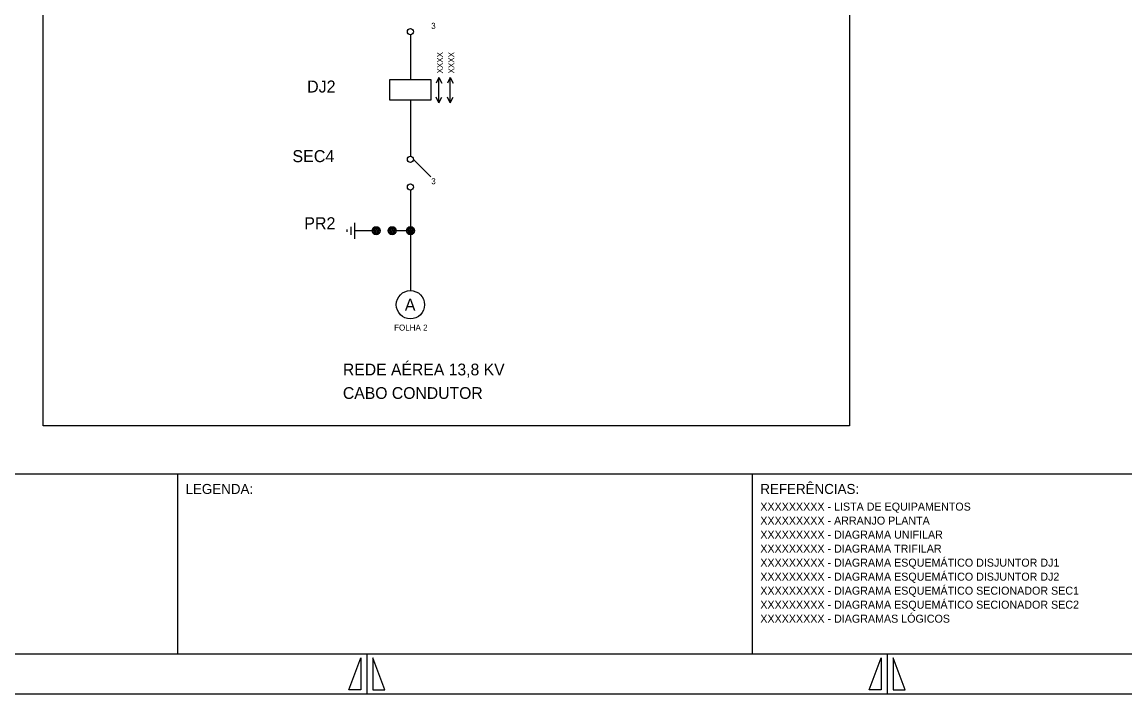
# Model space of a CAD drawing. Extents: x 563 to 1404, y 358 to 952.
# Drawn here: x 817.4 to 1093.1, y 358 to 525.8 of the extents above; entities that cross this region are included whole.
import ezdxf

# ---------------------------------------------------------------- set-up
doc = ezdxf.new("R2010")
doc.units = 0
doc.layers.add('New Level (0)', color=7, linetype='Continuous')

msp = doc.modelspace()

# ---------------------------------------------------------------- linework, layer by layer
for p, q in [((909.34, 506.3), (909.34, 511.42)), ((909.34, 511.42), (919.58, 511.42)), ((919.58, 511.42), (919.58, 506.3)), ((921.58, 511.96), (920.87, 510.55)), ((921.58, 505.6), (921.58, 511.96)), ((921.58, 511.96), (922.28, 510.55)), ((924.43, 511.96), (923.72, 510.55)), ((924.43, 505.6), (924.43, 511.96)), ((924.43, 511.96), (925.13, 510.55)), ((919.58, 506.3), (909.34, 506.3)), ((921.58, 505.6), (920.87, 507.01)), ((921.58, 505.6), (922.28, 507.01)), ((924.43, 505.6), (923.72, 507.01)), ((924.43, 505.6), (925.13, 507.01)), ((919.57, 487.15), (915.23, 491.49)), ((899.57, 474.68), (899.57, 472.68)), ((900.57, 471.68), (900.57, 475.68)), ((898.57, 473.98), (898.57, 473.38)), ((898.57, 473.68), (898.57, 473.68)), ((901.89, 473.68), (900.57, 473.68)), ((905.89, 473.68), (901.89, 473.68)), ((914.47, 473.68), (909.89, 473.68))]:
    msp.add_line(p, q)
for centre, radius in [((914.46, 523.39), 0.768), ((914.46, 491.49), 0.768), ((914.46, 484.59), 0.768), ((905.89, 473.68), 1), ((905.89, 473.68), 0.75), ((905.89, 473.68), 0.5), ((909.89, 473.68), 1), ((909.89, 473.68), 0.75), ((909.89, 473.68), 0.5), ((914.47, 473.68), 1), ((914.47, 473.68), 0.75), ((914.47, 473.68), 0.5), ((905.89, 473.68), 0.25), ((909.89, 473.68), 0.25), ((914.47, 473.68), 0.25)]:
    msp.add_circle(centre, radius)
at = {"layer": 'New Level (0)'}
for p, q in [((914.46, 522.63), (914.46, 511.42)), ((914.46, 506.3), (914.46, 492.26)), ((914.46, 483.82), (914.46, 458.73)), ((572.58, 412.96), (1393.58, 412.96)), ((856.24, 412.96), (856.24, 367.96)), ((999.91, 412.96), (999.91, 367.96)), ((572.58, 367.96), (1393.58, 367.96)), ((572.58, 367.96), (1393.58, 367.96)), ((899.08, 358.96), (902.08, 366.96)), ((902.08, 366.96), (902.08, 358.96)), ((903.58, 367.96), (903.58, 357.96)), ((905.08, 366.96), (905.08, 358.96)), ((908.08, 358.96), (905.08, 366.96)), ((1029.08, 358.96), (1032.08, 366.96)), ((1032.08, 366.96), (1032.08, 358.96)), ((1033.58, 367.96), (1033.58, 357.96)), ((1035.08, 366.96), (1035.08, 358.96)), ((1038.08, 358.96), (1035.08, 366.96)), ((902.08, 358.96), (899.08, 358.96)), ((905.08, 358.96), (908.08, 358.96)), ((1032.08, 358.96), (1029.08, 358.96)), ((1035.08, 358.96), (1038.08, 358.96)), ((562.58, 357.96), (1403.58, 357.96)), ((562.58, 357.96), (1403.58, 357.96))]:
    msp.add_line(p, q, dxfattribs=at)
msp.add_lwpolyline([(822.69, 674.35), (1024.17, 674.35), (1024.17, 424.93), (822.69, 424.93)], close=True, dxfattribs=at)
msp.add_circle((914.46, 455.18), 3.54, dxfattribs=at)

# ---------------------------------------------------------------- texts
for s, height, p in [('3', 1.5, (919.65, 524.1)), ('DJ2', 3, (888.62, 508.19)), ('SEC4', 3, (884.96, 490.8)), ('3', 1.5, (919.66, 485.29)), ('PR2', 3, (887.91, 474.04)), ('A', 3, (913.05, 453.68)), ('FOLHA 2', 1.5, (910.38, 448.72)), ('REDE AÉREA 13,8 KV', 2.94, (897.58, 437.53)), ('CABO CONDUTOR ', 2.94, (897.58, 431.65))]:
    msp.add_text(s, height=height).set_placement(p)
for p in [(922.58, 512.96), (925.43, 512.96)]:
    msp.add_text('XXXX', height=1.5, rotation=90).set_placement(p)
for s, height, p in [('REFERÊNCIAS:', 2.5, (1001.91, 407.91)), ('LEGENDA:', 2.5, (858.24, 407.91)), ('XXXXXXXXX - LISTA DE EQUIPAMENTOS', 2, (1001.91, 403.75)), ('XXXXXXXXX - ARRANJO PLANTA', 2, (1001.91, 400.25)), ('XXXXXXXXX - DIAGRAMA UNIFILAR', 2, (1001.91, 396.75)), ('XXXXXXXXX - DIAGRAMA TRIFILAR', 2, (1001.91, 393.25)), ('XXXXXXXXX - DIAGRAMA ESQUEMÁTICO DISJUNTOR DJ1', 2, (1001.91, 389.75)), ('XXXXXXXXX - DIAGRAMA ESQUEMÁTICO DISJUNTOR DJ2', 2, (1001.91, 386.25)), ('XXXXXXXXX - DIAGRAMA ESQUEMÁTICO SECIONADOR SEC1', 2, (1001.91, 382.75)), ('XXXXXXXXX - DIAGRAMA ESQUEMÁTICO SECIONADOR SEC2', 2, (1001.91, 379.25)), ('XXXXXXXXX - DIAGRAMAS LÓGICOS', 2, (1001.91, 375.75))]:
    msp.add_text(s, height=height, dxfattribs=at).set_placement(p)

doc.saveas('drawing.dxf')
